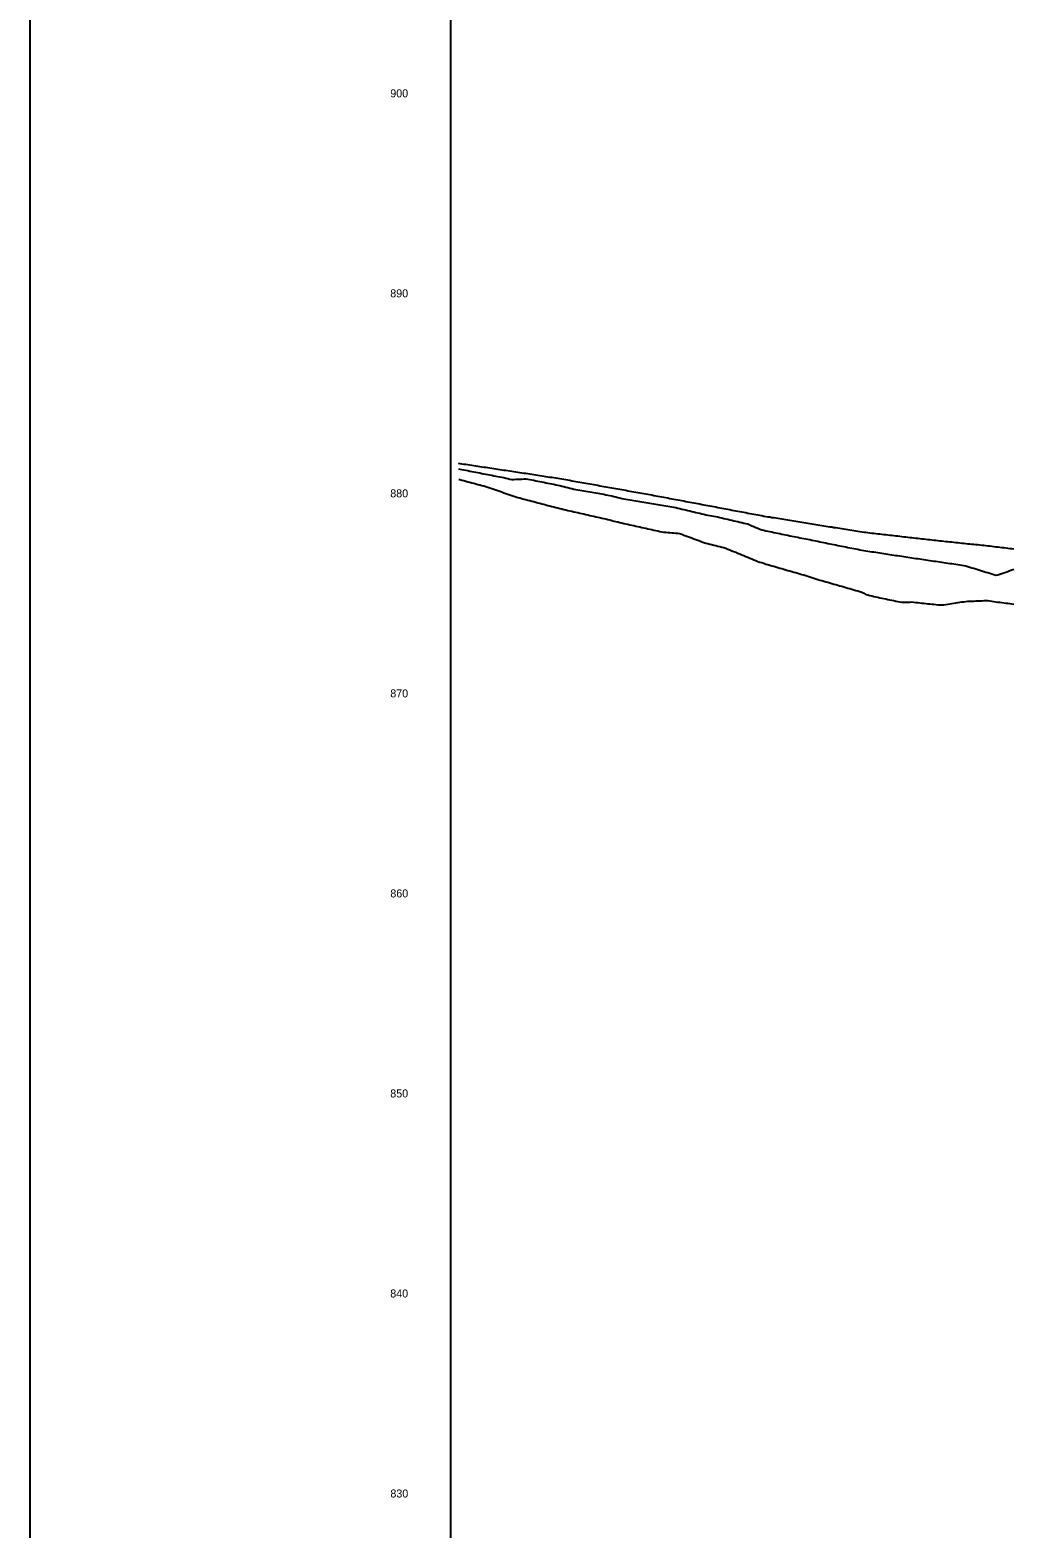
# Model space of a CAD drawing. Extents: x 1733669 to 1739080, y 1214897 to 1219897.
# Drawn here: x 1733669 to 1734161, y 1217684 to 1218432 of the extents above; entities that cross this region are included whole.
import ezdxf

# ---------------------------------------------------------------- set-up
doc = ezdxf.new("R2010")
doc.units = 0
for name, color, linetype in [('Default', 7, 'Continuous'), ('RD_DDB_ElevTX', 7, 'Continuous'), ('RD_DDB_Profile_EX', 7, 'Continuous'), ('RD_Sketch1', 7, 'Continuous'), ('RD_Sketch2', 7, 'Continuous'), ('RD_Sketch8', 7, 'Continuous')]:
    doc.layers.add(name, color=color, linetype=linetype)

msp = doc.modelspace()

# ---------------------------------------------------------------- linework, layer by layer
at = {"layer": 'Default'}
msp.add_line((1733879.77, 1217396.77), (1733879.77, 1219896.77), dxfattribs=at)
at = {"layer": 'RD_DDB_Profile_EX'}
for points in [[(1733883.46, 1218215.9), (1733884.3, 1218215.77), (1733885.3, 1218215.6), (1733886.3, 1218215.44), (1733887.3, 1218215.29), (1733888.3, 1218215.14), (1733889.3, 1218214.99), (1733890.3, 1218214.84), (1733891.3, 1218214.7), (1733892.3, 1218214.55), (1733893.3, 1218214.4), (1733894.3, 1218214.25), (1733895.3, 1218214.1), (1733896.3, 1218213.95), (1733897.3, 1218213.8), (1733898.3, 1218213.65), (1733899.3, 1218213.5), (1733900.3, 1218213.35), (1733901.3, 1218213.2), (1733902.3, 1218213.05), (1733903.3, 1218212.9), (1733904.3, 1218212.75), (1733905.3, 1218212.6), (1733906.3, 1218212.45), (1733907.3, 1218212.3), (1733908.3, 1218212.15), (1733909.3, 1218212), (1733910.3, 1218211.84), (1733911.3, 1218211.69), (1733912.3, 1218211.54), (1733913.3, 1218211.39), (1733914.3, 1218211.24), (1733915.3, 1218211.09), (1733916.3, 1218210.94), (1733917.3, 1218210.79), (1733918.3, 1218210.63), (1733919.3, 1218210.48), (1733920.3, 1218210.33), (1733921.3, 1218210.18), (1733922.3, 1218210.03), (1733923.3, 1218209.87), (1733924.3, 1218209.72), (1733925.3, 1218209.57), (1733926.3, 1218209.41), (1733927.3, 1218209.26), (1733928.3, 1218209.11), (1733929.3, 1218208.95), (1733930.3, 1218208.8), (1733931.3, 1218208.64), (1733932.3, 1218208.49), (1733933.3, 1218208.33), (1733934.3, 1218208.18), (1733935.3, 1218208.01), (1733936.3, 1218207.84), (1733937.3, 1218207.66), (1733938.3, 1218207.48), (1733939.3, 1218207.3), (1733940.3, 1218207.12), (1733941.3, 1218206.94), (1733942.3, 1218206.76), (1733943.3, 1218206.58), (1733944.3, 1218206.4), (1733945.3, 1218206.23), (1733946.3, 1218206.05), (1733947.3, 1218205.87), (1733948.3, 1218205.69), (1733949.3, 1218205.51), (1733950.3, 1218205.33), (1733951.3, 1218205.15), (1733952.3, 1218204.97), (1733953.3, 1218204.79), (1733954.3, 1218204.62), (1733955.3, 1218204.44), (1733956.3, 1218204.26), (1733957.3, 1218204.08), (1733958.3, 1218203.9), (1733959.3, 1218203.72), (1733960.3, 1218203.54), (1733961.3, 1218203.36), (1733962.3, 1218203.18), (1733963.3, 1218203), (1733964.3, 1218202.82), (1733965.3, 1218202.64), (1733966.3, 1218202.46), (1733967.3, 1218202.29), (1733968.3, 1218202.11), (1733969.3, 1218201.93), (1733970.3, 1218201.75), (1733971.3, 1218201.57), (1733972.3, 1218201.39), (1733973.3, 1218201.21), (1733974.3, 1218201.03), (1733975.3, 1218200.85), (1733976.3, 1218200.67), (1733977.3, 1218200.5), (1733978.3, 1218200.32), (1733979.3, 1218200.14), (1733980.3, 1218199.96), (1733981.3, 1218199.78), (1733982.3, 1218199.6), (1733983.3, 1218199.42)], [(1733983.3, 1218199.42), (1733984.3, 1218199.24), (1733985.3, 1218199.05), (1733986.3, 1218198.86), (1733987.3, 1218198.67), (1733988.3, 1218198.48), (1733989.3, 1218198.29), (1733990.3, 1218198.1), (1733991.3, 1218197.91), (1733992.3, 1218197.73), (1733993.3, 1218197.54), (1733994.3, 1218197.35), (1733995.3, 1218197.16), (1733996.3, 1218196.97), (1733997.3, 1218196.78), (1733998.3, 1218196.6), (1733999.3, 1218196.41), (1734000.3, 1218196.22), (1734001.3, 1218196.03), (1734002.3, 1218195.84), (1734003.3, 1218195.65), (1734004.3, 1218195.47), (1734005.3, 1218195.28), (1734006.3, 1218195.09), (1734007.3, 1218194.9), (1734008.3, 1218194.71), (1734009.3, 1218194.52), (1734010.3, 1218194.34), (1734011.3, 1218194.15), (1734012.3, 1218193.96), (1734013.3, 1218193.77), (1734014.3, 1218193.58), (1734015.3, 1218193.39), (1734016.3, 1218193.2), (1734017.3, 1218193.01), (1734018.3, 1218192.83), (1734019.3, 1218192.64), (1734020.3, 1218192.45), (1734021.3, 1218192.26), (1734022.3, 1218192.07), (1734023.3, 1218191.89), (1734024.3, 1218191.7), (1734025.3, 1218191.51), (1734026.3, 1218191.32), (1734027.3, 1218191.13), (1734028.3, 1218190.94), (1734029.3, 1218190.76), (1734030.3, 1218190.57), (1734031.3, 1218190.38), (1734032.3, 1218190.19), (1734033.3, 1218190), (1734034.3, 1218189.82), (1734035.3, 1218189.63), (1734036.3, 1218189.44), (1734037.3, 1218189.28), (1734038.3, 1218189.12), (1734039.3, 1218188.96), (1734040.3, 1218188.79), (1734041.3, 1218188.63), (1734042.3, 1218188.47), (1734043.3, 1218188.31), (1734044.3, 1218188.14), (1734045.3, 1218187.98), (1734046.3, 1218187.82), (1734047.3, 1218187.66), (1734048.3, 1218187.49), (1734049.3, 1218187.33), (1734050.3, 1218187.17), (1734051.3, 1218187.01), (1734052.3, 1218186.84), (1734053.3, 1218186.68), (1734054.3, 1218186.52), (1734055.3, 1218186.36), (1734056.3, 1218186.19), (1734057.3, 1218186.03), (1734058.3, 1218185.87), (1734059.3, 1218185.71), (1734060.3, 1218185.54), (1734061.3, 1218185.4), (1734062.3, 1218185.25), (1734063.3, 1218185.09), (1734064.3, 1218184.92), (1734065.3, 1218184.76), (1734066.3, 1218184.6), (1734067.3, 1218184.44), (1734068.3, 1218184.28), (1734069.3, 1218184.12), (1734070.3, 1218183.96), (1734071.3, 1218183.79), (1734072.3, 1218183.63), (1734073.3, 1218183.47), (1734074.3, 1218183.31), (1734075.3, 1218183.15), (1734076.3, 1218182.99), (1734077.3, 1218182.83), (1734078.3, 1218182.66), (1734079.3, 1218182.5), (1734080.3, 1218182.34), (1734081.3, 1218182.18), (1734082.3, 1218182.02), (1734083.3, 1218181.86)], [(1734083.3, 1218181.86), (1734084.3, 1218181.7), (1734085.3, 1218181.55), (1734086.3, 1218181.42), (1734087.3, 1218181.3), (1734088.3, 1218181.18), (1734089.3, 1218181.07), (1734090.3, 1218180.95), (1734091.3, 1218180.83), (1734092.3, 1218180.72), (1734093.3, 1218180.6), (1734094.3, 1218180.49), (1734095.3, 1218180.37), (1734096.3, 1218180.26), (1734097.3, 1218180.14), (1734098.3, 1218180.03), (1734099.3, 1218179.91), (1734100.3, 1218179.8), (1734101.3, 1218179.68), (1734102.3, 1218179.57), (1734103.3, 1218179.46), (1734104.3, 1218179.34), (1734105.3, 1218179.23), (1734106.3, 1218179.12), (1734107.3, 1218179), (1734108.3, 1218178.89), (1734109.3, 1218178.78), (1734110.3, 1218178.67), (1734111.3, 1218178.55), (1734112.3, 1218178.44), (1734113.3, 1218178.33), (1734114.3, 1218178.22), (1734115.3, 1218178.11), (1734116.3, 1218177.99), (1734117.3, 1218177.88), (1734118.3, 1218177.77), (1734119.3, 1218177.66), (1734120.3, 1218177.55), (1734121.3, 1218177.44), (1734122.3, 1218177.33), (1734123.3, 1218177.22), (1734124.3, 1218177.11), (1734125.3, 1218177), (1734126.3, 1218176.89), (1734127.3, 1218176.79), (1734128.3, 1218176.68), (1734129.3, 1218176.57), (1734130.3, 1218176.46), (1734131.3, 1218176.35), (1734132.3, 1218176.24), (1734133.3, 1218176.14), (1734134.3, 1218176.03), (1734135.3, 1218175.92), (1734136.3, 1218175.81), (1734137.3, 1218175.71), (1734138.3, 1218175.6), (1734139.3, 1218175.48), (1734140.3, 1218175.42), (1734141.3, 1218175.35), (1734142.3, 1218175.28), (1734143.3, 1218175.16), (1734144.3, 1218175.05), (1734145.3, 1218174.93), (1734146.3, 1218174.81), (1734147.3, 1218174.69), (1734148.3, 1218174.58), (1734149.3, 1218174.46), (1734150.3, 1218174.34), (1734151.3, 1218174.22), (1734152.3, 1218174.11), (1734153.3, 1218173.99), (1734154.3, 1218173.87), (1734155.3, 1218173.76), (1734156.3, 1218173.64), (1734157.3, 1218173.52), (1734158.3, 1218173.41), (1734159.3, 1218173.29), (1734160.3, 1218173.18), (1734161.3, 1218173.06)]]:
    msp.add_lwpolyline(points, dxfattribs=at)
at = {"layer": 'RD_Sketch1'}
for points in [[(1733883.6, 1218213.06), (1733884.3, 1218212.92), (1733885.3, 1218212.73), (1733886.3, 1218212.53), (1733887.3, 1218212.34), (1733888.3, 1218212.14), (1733889.3, 1218211.95), (1733890.3, 1218211.76), (1733891.3, 1218211.56), (1733892.3, 1218211.37), (1733893.3, 1218211.17), (1733894.3, 1218210.98), (1733895.3, 1218210.78), (1733896.3, 1218210.59), (1733897.3, 1218210.39), (1733898.3, 1218210.2), (1733899.3, 1218210), (1733900.3, 1218209.81), (1733901.3, 1218209.61), (1733902.3, 1218209.42), (1733903.3, 1218209.22), (1733904.3, 1218209.02), (1733905.3, 1218208.83), (1733906.3, 1218208.63), (1733907.3, 1218208.41), (1733908.3, 1218208.15), (1733909.3, 1218207.9), (1733910.3, 1218207.74), (1733911.3, 1218207.78), (1733912.3, 1218207.82), (1733913.3, 1218207.86), (1733914.3, 1218207.9), (1733915.3, 1218207.94), (1733916.3, 1218207.98), (1733917.3, 1218208.02), (1733918.3, 1218207.89), (1733919.3, 1218207.7), (1733920.3, 1218207.5), (1733921.3, 1218207.3), (1733922.3, 1218207.1), (1733923.3, 1218206.9), (1733924.3, 1218206.71), (1733925.3, 1218206.51), (1733926.3, 1218206.31), (1733927.3, 1218206.11), (1733928.3, 1218205.91), (1733929.3, 1218205.71), (1733930.3, 1218205.51), (1733931.3, 1218205.31), (1733932.3, 1218205.11), (1733933.3, 1218204.9), (1733934.3, 1218204.67), (1733935.3, 1218204.43), (1733936.3, 1218204.18), (1733937.3, 1218203.93), (1733938.3, 1218203.68), (1733939.3, 1218203.43), (1733940.3, 1218203.18), (1733941.3, 1218202.94), (1733942.3, 1218202.71), (1733943.3, 1218202.54), (1733944.3, 1218202.37), (1733945.3, 1218202.19), (1733946.3, 1218202.02), (1733947.3, 1218201.85), (1733948.3, 1218201.68), (1733949.3, 1218201.5), (1733950.3, 1218201.33), (1733951.3, 1218201.16), (1733952.3, 1218200.99), (1733953.3, 1218200.81), (1733954.3, 1218200.64), (1733955.3, 1218200.47), (1733956.3, 1218200.3), (1733957.3, 1218200.12), (1733958.3, 1218199.95), (1733959.3, 1218199.74), (1733960.3, 1218199.5), (1733961.3, 1218199.26), (1733962.3, 1218199.02), (1733963.3, 1218198.78), (1733964.3, 1218198.53), (1733965.3, 1218198.29), (1733966.3, 1218198.12), (1733967.3, 1218197.95), (1733968.3, 1218197.78), (1733969.3, 1218197.61), (1733970.3, 1218197.44), (1733971.3, 1218197.27), (1733972.3, 1218197.11), (1733973.3, 1218196.94), (1733974.3, 1218196.77), (1733975.3, 1218196.6), (1733976.3, 1218196.43), (1733977.3, 1218196.26), (1733978.3, 1218196.09), (1733979.3, 1218195.93), (1733980.3, 1218195.76), (1733981.3, 1218195.59), (1733982.3, 1218195.42), (1733983.3, 1218195.25)], [(1733983.3, 1218195.25), (1733984.3, 1218195.07), (1733985.3, 1218194.9), (1733986.3, 1218194.74), (1733987.3, 1218194.57), (1733988.3, 1218194.4), (1733989.3, 1218194.23), (1733990.3, 1218194.07), (1733991.3, 1218193.87), (1733992.3, 1218193.63), (1733993.3, 1218193.4), (1733994.3, 1218193.16), (1733995.3, 1218192.93), (1733996.3, 1218192.69), (1733997.3, 1218192.46), (1733998.3, 1218192.22), (1733999.3, 1218191.99), (1734000.3, 1218191.75), (1734001.3, 1218191.52), (1734002.3, 1218191.28), (1734003.3, 1218191.05), (1734004.3, 1218190.81), (1734005.3, 1218190.58), (1734006.3, 1218190.34), (1734007.3, 1218190.11), (1734008.3, 1218189.87), (1734009.3, 1218189.68), (1734010.3, 1218189.53), (1734011.3, 1218189.38), (1734012.3, 1218189.2), (1734013.3, 1218188.97), (1734014.3, 1218188.73), (1734015.3, 1218188.5), (1734016.3, 1218188.27), (1734017.3, 1218188.03), (1734018.3, 1218187.8), (1734019.3, 1218187.56), (1734020.3, 1218187.33), (1734021.3, 1218187.09), (1734022.3, 1218186.86), (1734023.3, 1218186.63), (1734024.3, 1218186.39), (1734025.3, 1218186.16), (1734026.3, 1218185.92), (1734027.3, 1218185.69), (1734028.3, 1218185.46), (1734029.3, 1218185.05), (1734030.3, 1218184.62), (1734031.3, 1218184.19), (1734032.3, 1218183.76), (1734033.3, 1218183.33), (1734034.3, 1218182.91), (1734035.3, 1218182.54), (1734036.3, 1218182.3), (1734037.3, 1218182.09), (1734038.3, 1218181.88), (1734039.3, 1218181.67), (1734040.3, 1218181.47), (1734041.3, 1218181.26), (1734042.3, 1218181.05), (1734043.3, 1218180.84), (1734044.3, 1218180.64), (1734045.3, 1218180.43), (1734046.3, 1218180.22), (1734047.3, 1218180.01), (1734048.3, 1218179.8), (1734049.3, 1218179.6), (1734050.3, 1218179.4), (1734051.3, 1218179.2), (1734052.3, 1218179), (1734053.3, 1218178.81), (1734054.3, 1218178.61), (1734055.3, 1218178.41), (1734056.3, 1218178.22), (1734057.3, 1218178.02), (1734058.3, 1218177.83), (1734059.3, 1218177.63), (1734060.3, 1218177.43), (1734061.3, 1218177.24), (1734062.3, 1218177.03), (1734063.3, 1218176.82), (1734064.3, 1218176.62), (1734065.3, 1218176.41), (1734066.3, 1218176.2), (1734067.3, 1218176), (1734068.3, 1218175.79), (1734069.3, 1218175.58), (1734070.3, 1218175.38), (1734071.3, 1218175.17), (1734072.3, 1218174.96), (1734073.3, 1218174.76), (1734074.3, 1218174.56), (1734075.3, 1218174.36), (1734076.3, 1218174.16), (1734077.3, 1218173.96), (1734078.3, 1218173.77), (1734079.3, 1218173.57), (1734080.3, 1218173.38), (1734081.3, 1218173.19), (1734082.3, 1218172.99), (1734083.3, 1218172.8)], [(1734083.3, 1218172.8), (1734084.3, 1218172.61), (1734085.3, 1218172.42), (1734086.3, 1218172.24), (1734087.3, 1218172.09), (1734088.3, 1218171.93), (1734089.3, 1218171.78), (1734090.3, 1218171.62), (1734091.3, 1218171.47), (1734092.3, 1218171.32), (1734093.3, 1218171.16), (1734094.3, 1218171.01), (1734095.3, 1218170.86), (1734096.3, 1218170.7), (1734097.3, 1218170.55), (1734098.3, 1218170.4), (1734099.3, 1218170.25), (1734100.3, 1218170.09), (1734101.3, 1218169.94), (1734102.3, 1218169.79), (1734103.3, 1218169.64), (1734104.3, 1218169.48), (1734105.3, 1218169.33), (1734106.3, 1218169.18), (1734107.3, 1218169.03), (1734108.3, 1218168.88), (1734109.3, 1218168.73), (1734110.3, 1218168.57), (1734111.3, 1218168.42), (1734112.3, 1218168.28), (1734113.3, 1218168.13), (1734114.3, 1218167.98), (1734115.3, 1218167.83), (1734116.3, 1218167.68), (1734117.3, 1218167.53), (1734118.3, 1218167.39), (1734119.3, 1218167.24), (1734120.3, 1218167.09), (1734121.3, 1218166.94), (1734122.3, 1218166.8), (1734123.3, 1218166.65), (1734124.3, 1218166.51), (1734125.3, 1218166.36), (1734126.3, 1218166.21), (1734127.3, 1218166.07), (1734128.3, 1218165.92), (1734129.3, 1218165.78), (1734130.3, 1218165.63), (1734131.3, 1218165.48), (1734132.3, 1218165.34), (1734133.3, 1218165.19), (1734134.3, 1218165.05), (1734135.3, 1218164.9), (1734136.3, 1218164.76), (1734137.3, 1218164.56), (1734138.3, 1218164.25), (1734139.3, 1218163.93), (1734140.3, 1218163.62), (1734141.3, 1218163.31), (1734142.3, 1218163), (1734143.3, 1218162.69), (1734144.3, 1218162.38), (1734145.3, 1218162.06), (1734146.3, 1218161.75), (1734147.3, 1218161.44), (1734148.3, 1218161.13), (1734149.3, 1218160.82), (1734150.3, 1218160.51), (1734151.3, 1218160.2), (1734152.3, 1218159.89), (1734153.3, 1218159.98), (1734154.3, 1218160.34), (1734155.3, 1218160.7), (1734156.3, 1218161.06), (1734157.3, 1218161.43), (1734158.3, 1218161.79), (1734159.3, 1218162.16), (1734160.3, 1218162.53), (1734161.3, 1218162.91)]]:
    msp.add_lwpolyline(points, dxfattribs=at)
at = {"layer": 'RD_Sketch2'}
for points in [[(1733883.87, 1218207.81), (1733884.3, 1218207.69), (1733885.3, 1218207.42), (1733886.3, 1218207.15), (1733887.3, 1218206.88), (1733888.3, 1218206.62), (1733889.3, 1218206.35), (1733890.3, 1218206.08), (1733891.3, 1218205.81), (1733892.3, 1218205.55), (1733893.3, 1218205.28), (1733894.3, 1218205.01), (1733895.3, 1218204.74), (1733896.3, 1218204.47), (1733897.3, 1218204.21), (1733898.3, 1218203.87), (1733899.3, 1218203.52), (1733900.3, 1218203.18), (1733901.3, 1218202.83), (1733902.3, 1218202.49), (1733903.3, 1218202.15), (1733904.3, 1218201.8), (1733905.3, 1218201.46), (1733906.3, 1218201.11), (1733907.3, 1218200.77), (1733908.3, 1218200.42), (1733909.3, 1218200.08), (1733910.3, 1218199.73), (1733911.3, 1218199.39), (1733912.3, 1218199.05), (1733913.3, 1218198.72), (1733914.3, 1218198.46), (1733915.3, 1218198.2), (1733916.3, 1218197.94), (1733917.3, 1218197.68), (1733918.3, 1218197.42), (1733919.3, 1218197.15), (1733920.3, 1218196.89), (1733921.3, 1218196.63), (1733922.3, 1218196.37), (1733923.3, 1218196.11), (1733924.3, 1218195.84), (1733925.3, 1218195.58), (1733926.3, 1218195.32), (1733927.3, 1218195.06), (1733928.3, 1218194.79), (1733929.3, 1218194.53), (1733930.3, 1218194.27), (1733931.3, 1218194.01), (1733932.3, 1218193.74), (1733933.3, 1218193.48), (1733934.3, 1218193.22), (1733935.3, 1218192.96), (1733936.3, 1218192.73), (1733937.3, 1218192.51), (1733938.3, 1218192.28), (1733939.3, 1218192.05), (1733940.3, 1218191.83), (1733941.3, 1218191.6), (1733942.3, 1218191.37), (1733943.3, 1218191.15), (1733944.3, 1218190.92), (1733945.3, 1218190.69), (1733946.3, 1218190.46), (1733947.3, 1218190.24), (1733948.3, 1218190.01), (1733949.3, 1218189.78), (1733950.3, 1218189.56), (1733951.3, 1218189.33), (1733952.3, 1218189.1), (1733953.3, 1218188.88), (1733954.3, 1218188.65), (1733955.3, 1218188.42), (1733956.3, 1218188.19), (1733957.3, 1218187.96), (1733958.3, 1218187.71), (1733959.3, 1218187.46), (1733960.3, 1218187.2), (1733961.3, 1218186.95), (1733962.3, 1218186.7), (1733963.3, 1218186.47), (1733964.3, 1218186.24), (1733965.3, 1218186.02), (1733966.3, 1218185.79), (1733967.3, 1218185.57), (1733968.3, 1218185.34), (1733969.3, 1218185.12), (1733970.3, 1218184.89), (1733971.3, 1218184.67), (1733972.3, 1218184.44), (1733973.3, 1218184.21), (1733974.3, 1218183.99), (1733975.3, 1218183.76), (1733976.3, 1218183.54), (1733977.3, 1218183.31), (1733978.3, 1218183.09), (1733979.3, 1218182.86), (1733980.3, 1218182.64), (1733981.3, 1218182.41), (1733982.3, 1218182.19), (1733983.3, 1218181.96)], [(1733983.3, 1218181.96), (1733984.3, 1218181.74), (1733985.3, 1218181.51), (1733986.3, 1218181.38), (1733987.3, 1218181.31), (1733988.3, 1218181.24), (1733989.3, 1218181.17), (1733990.3, 1218181.09), (1733991.3, 1218181.02), (1733992.3, 1218180.95), (1733993.3, 1218180.88), (1733994.3, 1218180.67), (1733995.3, 1218180.3), (1733996.3, 1218179.93), (1733997.3, 1218179.56), (1733998.3, 1218179.19), (1733999.3, 1218178.83), (1734000.3, 1218178.46), (1734001.3, 1218178.09), (1734002.3, 1218177.72), (1734003.3, 1218177.35), (1734004.3, 1218176.98), (1734005.3, 1218176.61), (1734006.3, 1218176.24), (1734007.3, 1218175.91), (1734008.3, 1218175.66), (1734009.3, 1218175.41), (1734010.3, 1218175.16), (1734011.3, 1218174.92), (1734012.3, 1218174.67), (1734013.3, 1218174.42), (1734014.3, 1218174.17), (1734015.3, 1218173.92), (1734016.3, 1218173.68), (1734017.3, 1218173.36), (1734018.3, 1218172.95), (1734019.3, 1218172.54), (1734020.3, 1218172.12), (1734021.3, 1218171.71), (1734022.3, 1218171.3), (1734023.3, 1218170.89), (1734024.3, 1218170.48), (1734025.3, 1218170.07), (1734026.3, 1218169.66), (1734027.3, 1218169.25), (1734028.3, 1218168.84), (1734029.3, 1218168.43), (1734030.3, 1218168.02), (1734031.3, 1218167.61), (1734032.3, 1218167.19), (1734033.3, 1218166.78), (1734034.3, 1218166.38), (1734035.3, 1218166.14), (1734036.3, 1218165.83), (1734037.3, 1218165.46), (1734038.3, 1218165.17), (1734039.3, 1218164.89), (1734040.3, 1218164.6), (1734041.3, 1218164.31), (1734042.3, 1218164.02), (1734043.3, 1218163.73), (1734044.3, 1218163.45), (1734045.3, 1218163.16), (1734046.3, 1218162.87), (1734047.3, 1218162.58), (1734048.3, 1218162.29), (1734049.3, 1218162.01), (1734050.3, 1218161.72), (1734051.3, 1218161.43), (1734052.3, 1218161.14), (1734053.3, 1218160.85), (1734054.3, 1218160.56), (1734055.3, 1218160.28), (1734056.3, 1218159.99), (1734057.3, 1218159.7), (1734058.3, 1218159.41), (1734059.3, 1218159.09), (1734060.3, 1218158.72), (1734061.3, 1218158.34), (1734062.3, 1218158.02), (1734063.3, 1218157.73), (1734064.3, 1218157.45), (1734065.3, 1218157.16), (1734066.3, 1218156.88), (1734067.3, 1218156.59), (1734068.3, 1218156.31), (1734069.3, 1218156.02), (1734070.3, 1218155.74), (1734071.3, 1218155.45), (1734072.3, 1218155.17), (1734073.3, 1218154.88), (1734074.3, 1218154.6), (1734075.3, 1218154.31), (1734076.3, 1218154.03), (1734077.3, 1218153.74), (1734078.3, 1218153.45), (1734079.3, 1218153.16), (1734080.3, 1218152.87), (1734081.3, 1218152.58), (1734082.3, 1218152.28), (1734083.3, 1218151.99)], [(1734083.3, 1218151.99), (1734084.3, 1218151.69), (1734085.3, 1218151.33), (1734086.3, 1218150.83), (1734087.3, 1218150.26), (1734088.3, 1218149.99), (1734089.3, 1218149.75), (1734090.3, 1218149.52), (1734091.3, 1218149.29), (1734092.3, 1218149.07), (1734093.3, 1218148.84), (1734094.3, 1218148.62), (1734095.3, 1218148.4), (1734096.3, 1218148.18), (1734097.3, 1218147.97), (1734098.3, 1218147.75), (1734099.3, 1218147.54), (1734100.3, 1218147.34), (1734101.3, 1218147.13), (1734102.3, 1218146.93), (1734103.3, 1218146.73), (1734104.3, 1218146.53), (1734105.3, 1218146.33), (1734106.3, 1218146.3), (1734107.3, 1218146.35), (1734108.3, 1218146.39), (1734109.3, 1218146.44), (1734110.3, 1218146.5), (1734111.3, 1218146.42), (1734112.3, 1218146.29), (1734113.3, 1218146.17), (1734114.3, 1218146.06), (1734115.3, 1218145.94), (1734116.3, 1218145.83), (1734117.3, 1218145.72), (1734118.3, 1218145.61), (1734119.3, 1218145.51), (1734120.3, 1218145.41), (1734121.3, 1218145.31), (1734122.3, 1218145.22), (1734123.3, 1218145.12), (1734124.3, 1218145.03), (1734125.3, 1218144.98), (1734126.3, 1218145.12), (1734127.3, 1218145.26), (1734128.3, 1218145.41), (1734129.3, 1218145.56), (1734130.3, 1218145.72), (1734131.3, 1218145.87), (1734132.3, 1218146.03), (1734133.3, 1218146.2), (1734134.3, 1218146.36), (1734135.3, 1218146.53), (1734136.3, 1218146.59), (1734137.3, 1218146.64), (1734138.3, 1218146.82), (1734139.3, 1218146.85), (1734140.3, 1218146.89), (1734141.3, 1218146.93), (1734142.3, 1218146.97), (1734143.3, 1218147.02), (1734144.3, 1218147.07), (1734145.3, 1218147.12), (1734146.3, 1218147.17), (1734147.3, 1218147.23), (1734148.3, 1218147.14), (1734149.3, 1218146.99), (1734150.3, 1218146.85), (1734151.3, 1218146.71), (1734152.3, 1218146.57), (1734153.3, 1218146.43), (1734154.3, 1218146.3), (1734155.3, 1218146.17), (1734156.3, 1218146.05), (1734157.3, 1218145.92), (1734158.3, 1218145.8), (1734159.3, 1218145.68), (1734160.3, 1218145.57), (1734161.3, 1218145.46)]]:
    msp.add_lwpolyline(points, dxfattribs=at)
at = {"layer": 'RD_Sketch8'}
msp.add_lwpolyline([(1733669.38, 1216984.56), (1737269.38, 1216984.56), (1737269.38, 1219184.56), (1733669.38, 1219184.56)], close=True, dxfattribs=at)

# ---------------------------------------------------------------- texts
at = {"layer": 'RD_DDB_ElevTX'}
for s, p in [('900', (1733849.53, 1218398.77)), ('890', (1733849.53, 1218298.77)), ('880', (1733849.53, 1218198.77)), ('870', (1733849.53, 1218098.77)), ('860', (1733849.57, 1217998.77)), ('850', (1733849.53, 1217898.77)), ('840', (1733849.53, 1217798.77)), ('830', (1733849.59, 1217698.77))]:
    msp.add_text(s, height=4, dxfattribs=at).set_placement(p)

doc.saveas('drawing.dxf')
